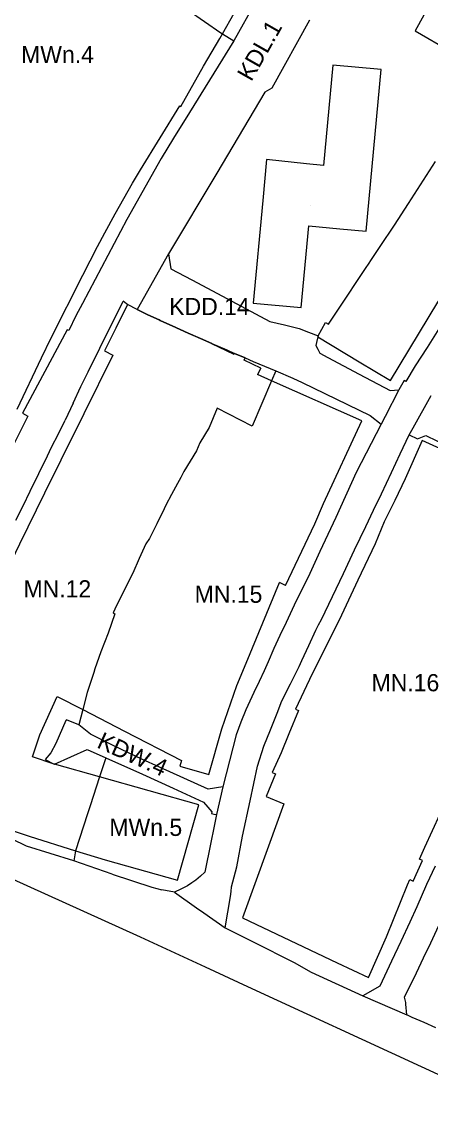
# Model space of a CAD drawing. Extents: x 7425067 to 7426806, y 5549054 to 5550619.
# Drawn here: x 7425656.7 to 7425775.6, y 5549655.4 to 5549976.3 of the extents above; entities that cross this region are included whole.
import ezdxf

# ---------------------------------------------------------------- set-up
doc = ezdxf.new("R2010")
doc.units = 0
for name, color, linetype in [('LIN_Linia Zabudowy Nieprzekraczalna', 7, 'Continuous'), ('LIN_linia zabudowy obowiązująca', 7, 'Continuous'), ('LIN_linie_rozgraniczajace', 7, 'Continuous'), ('TXT_Oznaczenia_przeznaczen', 7, 'Continuous')]:
    doc.layers.add(name, color=color, linetype=linetype)

msp = doc.modelspace()

# ---------------------------------------------------------------- linework, layer by layer
at = {"layer": 'LIN_Linia Zabudowy Nieprzekraczalna'}
for points in [[(7425742.7389, 5549884.8292), (7425754.78, 5549877.53), (7425763.82, 5549872.05), (7425777.59, 5549894.86), (7425782.97, 5549902.92), (7425793.7, 5549919.37), (7425798.37, 5549926.6), (7425805.55, 5549937.49), (7425810.05, 5549943.84), (7425813.5, 5549948.98), (7425818.04, 5549956.33), (7425822.22, 5549961.9), (7425831.24, 5549975.65), (7425835.44, 5549982.46), (7425845.17, 5549996.67), (7425848.22, 5550001.39), (7425860.25, 5550019.29)], [(7425688.8399, 5549929.4585), (7425691.2009, 5549933.3935), (7425702.6055, 5549951.9648), (7425702.86, 5549951.8), (7425709.48, 5549963.44), (7425710.7848, 5549965.653), (7425714.2539, 5549971.5633), (7425714.9902, 5549972.8797), (7425718.3675, 5549978.9183), (7425721.36, 5549984.23), (7425724.68, 5549989.11), (7425723.92, 5549989.66), (7425727.01, 5549994.19), (7425726.17, 5549994.77), (7425730.2813, 5550000.6279)], [(7425655.2768, 5549863.7294), (7425662.3503, 5549878.7355), (7425665.1746, 5549884.5158), (7425674.3584, 5549902.7629), (7425678.6779, 5549911.0696), (7425680.8016, 5549915.0743), (7425683.7745, 5549920.5636), (7425688.8399, 5549929.4585)], [(7425687.4166, 5549894.1603), (7425683.97, 5549887.33), (7425680.6584, 5549880.7578), (7425683.144, 5549879.4729)], [(7425726.15, 5549875.71), (7425721.3, 5549878.04), (7425721.5977, 5549878.6578), (7425718.5271, 5549879.9944), (7425718.36, 5549879.65), (7425711.86, 5549882.78), (7425711.9053, 5549882.8769), (7425708.59, 5549884.32), (7425704.98, 5549885.9), (7425700.35, 5549888.01), (7425699.66, 5549888.32), (7425696.87, 5549889.59), (7425696.5726, 5549889.7239), (7425693.25, 5549891.22), (7425690.155, 5549892.78), (7425687.4166, 5549894.1603)], [(7425683.144, 5549879.4729), (7425674.6885, 5549862.4106), (7425668.0393, 5549848.9323), (7425663.2786, 5549839.311), (7425655.9796, 5549824.5332), (7425648.9293, 5549809.9832), (7425646.0622, 5549804.0686), (7425642.7058, 5549797.2362), (7425636.6761, 5549784.4652)], [(7425726.15, 5549875.71), (7425725.2169, 5549873.8477)], [(7425755.5631, 5549860.3295), (7425729.2858, 5549872.0351), (7425725.2169, 5549873.8477)], [(7425733.37, 5549812.51), (7425741.88, 5549830.46), (7425744.41, 5549836.31), (7425755.5631, 5549860.3295)], [(7425773.11, 5549854.61), (7425768.09, 5549843.48), (7425765.11, 5549837.25), (7425762.06, 5549830.97), (7425759.4, 5549824.66), (7425754.35, 5549814.09), (7425749.57, 5549803.9), (7425746.41, 5549797.37), (7425741.09, 5549786.8), (7425736.24, 5549776.54), (7425737.1368, 5549776.1147)], [(7425779.596, 5549846.8457), (7425781.4, 5549850.92), (7425773.11, 5549854.61)], [(7425702.6, 5549759.97), (7425711.03, 5549757.56), (7425714.82, 5549770.83), (7425719.16, 5549783.44), (7425721.88, 5549789.88), (7425731.5999, 5549813.3544)], [(7425733.37, 5549812.51), (7425731.5999, 5549813.3544)], [(7425661.85, 5549769.11), (7425666.9725, 5549780.2432)], [(7425666.9725, 5549780.2432), (7425674.3987, 5549776.4089), (7425686.54, 5549770.14), (7425703.0633, 5549761.6086)], [(7425737.1368, 5549776.1147), (7425734.34, 5549769.4), (7425732.02, 5549763.83), (7425729.47, 5549758.13)], [(7425659.7764, 5549762.7317), (7425661.85, 5549769.11)], [(7425708.1, 5549748.75), (7425679.2737, 5549756.8742), (7425666.1673, 5549760.5777), (7425666.14, 5549760.57), (7425666.0929, 5549760.5928), (7425659.7764, 5549762.7317)], [(7425703.0633, 5549761.6086), (7425702.6, 5549759.97)], [(7425729.47, 5549758.13), (7425730.44, 5549757.74), (7425727.7, 5549751.2), (7425732.8299, 5549749.0202)], [(7425624.1991, 5549755.0945), (7425624.94, 5549754.67), (7425624.79, 5549753.35), (7425625.375, 5549753.025), (7425625.96, 5549752.7), (7425630.45, 5549750.59), (7425634.94, 5549748.48), (7425649.28, 5549742.72), (7425658.83, 5549739.66), (7425672.26, 5549735.38), (7425680.88, 5549732.76), (7425701.88, 5549726.85)], [(7425701.88, 5549726.85), (7425708.1, 5549748.75)], [(7425732.8299, 5549749.0202), (7425728.37, 5549736.75), (7425720.8009, 5549715.9258)], [(7425770.46, 5549726.57), (7425773.16, 5549732.55), (7425772.25, 5549732.96), (7425773.82, 5549736.43), (7425778.34, 5549746.1)], [(7425757.4618, 5549698.5049), (7425762.74, 5549710.31), (7425768.79, 5549725.5), (7425769.48, 5549727.01), (7425770.46, 5549726.57)], [(7425720.8009, 5549715.9258), (7425748.36, 5549702.83), (7425757.4618, 5549698.5049)]]:
    msp.add_lwpolyline(points, dxfattribs=at)
at = {"layer": 'LIN_linia zabudowy obowiązująca'}
for points in [[(7425827.66, 5550076.24), (7425771.07, 5549973.79)], [(7425771.07, 5549973.79), (7425781.44, 5549967.75), (7425838.25, 5550070.38), (7425827.66, 5550076.24)], [(7425761.17, 5549962.54), (7425747.06, 5549963.77), (7425744.3596, 5549934.5822), (7425739.39, 5549935.12), (7425727.84, 5549936.37), (7425726.71, 5549924.45), (7425723.95, 5549894.59)], [(7425740.1347, 5549917.0302), (7425749.154, 5549916.1833), (7425756.75, 5549915.47), (7425761.17, 5549962.54)], [(7425723.95, 5549894.59), (7425737.86, 5549893.33), (7425740.1347, 5549917.0302)]]:
    msp.add_lwpolyline(points, dxfattribs=at)
at = {"layer": 'LIN_linie_rozgraniczajace'}
for points in [[(7425724.58, 5549982.13), (7425718.26, 5549970.81)], [(7425705.05, 5549979.74), (7425714.5, 5549973.19)], [(7425740.32, 5549976.83), (7425729.34, 5549957.05)], [(7425714.5, 5549973.19), (7425714.9902, 5549972.8797), (7425718.26, 5549970.81)], [(7425718.26, 5549970.81), (7425705.42, 5549950.01)], [(7425727.33, 5549955.9), (7425713.33, 5549932.405)], [(7425729.34, 5549957.05), (7425727.33, 5549955.9)], [(7425705.42, 5549950.01), (7425700.73, 5549942.58)], [(7425700.73, 5549942.58), (7425697.2, 5549936.63)], [(7425697.2, 5549936.63), (7425687.22, 5549918.92)], [(7425769.12, 5549923.52), (7425776.93, 5549935.78)], [(7425713.33, 5549932.405), (7425699.33, 5549908.91)], [(7425764.985, 5549917.3), (7425769.12, 5549923.52)], [(7425687.22, 5549918.92), (7425674.26, 5549894.53)], [(7425760.85, 5549911.08), (7425764.985, 5549917.3)], [(7425758.14, 5549907.01), (7425760.85, 5549911.08)], [(7425699.33, 5549908.91), (7425690.155, 5549892.78)], [(7425699.33, 5549908.91), (7425699.97, 5549904.6)], [(7425757.61, 5549906.2), (7425758.14, 5549907.01)], [(7425699.97, 5549904.6), (7425706.055, 5549901.365)], [(7425754.49, 5549901.47), (7425756.59, 5549904.655)], [(7425756.59, 5549904.655), (7425757.61, 5549906.2)], [(7425706.055, 5549901.365), (7425712.14, 5549898.13)], [(7425750.88, 5549896.06), (7425754.49, 5549901.47)], [(7425712.14, 5549898.13), (7425720.47, 5549893.705)], [(7425674.26, 5549894.53), (7425672.31, 5549890.88)], [(7425679.3, 5549881.46), (7425686.14, 5549895.19)], [(7425687.06, 5549894.34), (7425686.14, 5549895.19)], [(7425690.155, 5549892.78), (7425687.4166, 5549894.1603), (7425687.06, 5549894.34)], [(7425745.86, 5549888.45), (7425750.88, 5549896.06)], [(7425672.31, 5549890.88), (7425670.34, 5549886.66)], [(7425690.155, 5549892.78), (7425693.25, 5549891.22)], [(7425693.25, 5549891.22), (7425696.5726, 5549889.7239), (7425696.87, 5549889.59)], [(7425720.47, 5549893.705), (7425728.8, 5549889.28)], [(7425696.87, 5549889.59), (7425699.66, 5549888.32)], [(7425699.66, 5549888.32), (7425700.35, 5549888.01)], [(7425700.35, 5549888.01), (7425704.98, 5549885.9)], [(7425728.8, 5549889.28), (7425733.04, 5549888.255)], [(7425733.04, 5549888.255), (7425737.28, 5549887.23)], [(7425742.79, 5549885.04), (7425744.93, 5549888.97)], [(7425744.93, 5549888.97), (7425745.86, 5549888.45)], [(7425669.85, 5549886.86), (7425656.82, 5549862.57)], [(7425670.34, 5549886.66), (7425669.85, 5549886.86)], [(7425704.98, 5549885.9), (7425706.42, 5549885.25)], [(7425706.42, 5549885.25), (7425708.59, 5549884.32)], [(7425737.28, 5549887.23), (7425740.035, 5549886.135)], [(7425740.035, 5549886.135), (7425742.79, 5549885.04)], [(7425742.79, 5549885.04), (7425742.7389, 5549884.8292), (7425742.32, 5549883.1)], [(7425777.9, 5549887.14), (7425774.54, 5549881.69)], [(7425675.98, 5549874.63), (7425679.3, 5549881.46)], [(7425708.59, 5549884.32), (7425711.9053, 5549882.8769), (7425716.24, 5549880.99)], [(7425742.32, 5549883.1), (7425742.12, 5549882.25)], [(7425742.12, 5549882.25), (7425742.72, 5549881.16)], [(7425774.54, 5549881.69), (7425771.07, 5549876.35)], [(7425716.24, 5549880.99), (7425718.5271, 5549879.9944), (7425721.5977, 5549878.6578), (7425723.89, 5549877.66)], [(7425742.72, 5549881.16), (7425743.32, 5549880.07)], [(7425743.32, 5549880.07), (7425745.6, 5549878.77)], [(7425745.6, 5549878.77), (7425754.705, 5549873.985)], [(7425730.5, 5549874.88), (7425729.2858, 5549872.0351), (7425723.65, 5549858.83)], [(7425723.89, 5549877.66), (7425727.195, 5549876.27)], [(7425727.195, 5549876.27), (7425730.5, 5549874.88)], [(7425730.5, 5549874.88), (7425735.47, 5549872.79)], [(7425771.07, 5549876.35), (7425768.29, 5549871.79)], [(7425673.84, 5549870.37), (7425675.98, 5549874.63)], [(7425735.47, 5549872.79), (7425738.16, 5549871.56)], [(7425738.16, 5549871.56), (7425757.9824, 5549861.8946)], [(7425754.705, 5549873.985), (7425763.81, 5549869.2)], [(7425767.8, 5549872.05), (7425766.26, 5549869.43)], [(7425768.29, 5549871.79), (7425767.8, 5549872.05)], [(7425671.55, 5549865.475), (7425673.84, 5549870.37)], [(7425766.26, 5549869.43), (7425762.28, 5549861.67)], [(7425763.81, 5549869.2), (7425765.035, 5549869.315)], [(7425765.035, 5549869.315), (7425766.26, 5549869.43)], [(7425671.55, 5549865.475), (7425669.26, 5549860.58)], [(7425770.44, 5549858.34), (7425775.65, 5549867.73)], [(7425656.82, 5549862.57), (7425658.37, 5549861.7)], [(7425713.47, 5549864.08), (7425711.09, 5549858.42)], [(7425723.65, 5549858.83), (7425713.47, 5549864.08)], [(7425658.37, 5549861.7), (7425654.19, 5549853.35)], [(7425667.285, 5549856.64), (7425669.26, 5549860.58)], [(7425762.28, 5549861.67), (7425761.1031, 5549859.3764), (7425753.89, 5549845.32)], [(7425757.9824, 5549861.8946), (7425761.1031, 5549859.3764)], [(7425665.31, 5549852.7), (7425667.285, 5549856.64)], [(7425709.775, 5549856.205), (7425708.46, 5549853.99)], [(7425711.09, 5549858.42), (7425709.775, 5549856.205)], [(7425766.705, 5549850.805), (7425769.28, 5549856.26)], [(7425769.28, 5549856.26), (7425770.44, 5549858.34)], [(7425769.28, 5549856.26), (7425771.69, 5549855.14)], [(7425771.69, 5549855.14), (7425774.16, 5549856.13)], [(7425774.16, 5549856.13), (7425783.69, 5549851.43)], [(7425664.695, 5549851.47), (7425665.31, 5549852.7)], [(7425708.46, 5549853.99), (7425707.43, 5549851.65)], [(7425661.585, 5549845.06), (7425664.08, 5549850.24)], [(7425664.08, 5549850.24), (7425664.695, 5549851.47)], [(7425707.43, 5549851.65), (7425705.615, 5549848.655)], [(7425764.13, 5549845.35), (7425766.705, 5549850.805)], [(7425705.615, 5549848.655), (7425703.8, 5549845.66)], [(7425659.09, 5549839.88), (7425661.585, 5549845.06)], [(7425702.855, 5549843.9), (7425701.91, 5549842.14)], [(7425703.8, 5549845.66), (7425702.855, 5549843.9)], [(7425753.89, 5549845.32), (7425747.93, 5549832.26)], [(7425762.7, 5549842.235), (7425764.13, 5549845.35)], [(7425656.99, 5549835.695), (7425659.09, 5549839.88)], [(7425701.91, 5549842.14), (7425700.215, 5549838.99)], [(7425761.27, 5549839.12), (7425762.7, 5549842.235)], [(7425700.215, 5549838.99), (7425698.52, 5549835.84)], [(7425758.96, 5549834.405), (7425761.27, 5549839.12)], [(7425654.89, 5549831.51), (7425656.99, 5549835.695)], [(7425698.01, 5549834.74), (7425695.87, 5549830.46)], [(7425698.52, 5549835.84), (7425698.01, 5549834.74)], [(7425756.65, 5549829.69), (7425758.96, 5549834.405)], [(7425695.87, 5549830.46), (7425693.73, 5549826.18)], [(7425747.93, 5549832.26), (7425743.28, 5549822.37)], [(7425753.4, 5549822.85), (7425756.65, 5549829.69)], [(7425692.67, 5549824.61), (7425690.795, 5549820.36)], [(7425693.73, 5549826.18), (7425692.67, 5549824.61)], [(7425690.795, 5549820.36), (7425688.92, 5549816.11)], [(7425743.28, 5549822.37), (7425740.37, 5549815.97)], [(7425750.15, 5549816.01), (7425753.4, 5549822.85)], [(7425688.92, 5549816.11), (7425684.19, 5549806.72)], [(7425740.37, 5549815.97), (7425735.82, 5549806.76)], [(7425746.95, 5549809.32), (7425750.15, 5549816.01)], [(7425743.75, 5549802.63), (7425746.95, 5549809.32)], [(7425683.69, 5549804.27), (7425681.71, 5549798.64)], [(7425684.19, 5549806.72), (7425683.21, 5549804.54)], [(7425683.21, 5549804.54), (7425683.69, 5549804.27)], [(7425734.65, 5549804.27), (7425733.48, 5549801.78)], [(7425735.82, 5549806.76), (7425734.65, 5549804.27)], [(7425733.48, 5549801.78), (7425731.695, 5549797.99)], [(7425742.12, 5549799.47), (7425742.935, 5549801.05)], [(7425742.935, 5549801.05), (7425743.75, 5549802.63)], [(7425681.71, 5549798.64), (7425679.63, 5549793.21)], [(7425731.695, 5549797.99), (7425729.91, 5549794.2)], [(7425740.115, 5549795.09), (7425742.12, 5549799.47)], [(7425738.11, 5549790.71), (7425740.115, 5549795.09)], [(7425679.63, 5549793.21), (7425677.85, 5549788.27)], [(7425729.91, 5549794.2), (7425728.25, 5549790.31)], [(7425677.85, 5549788.27), (7425677.54, 5549787.2)], [(7425728.25, 5549790.31), (7425727.16, 5549787.73)], [(7425734.755, 5549783.95), (7425737.3, 5549788.93)], [(7425737.3, 5549788.93), (7425738.11, 5549790.71)], [(7425677.54, 5549787.2), (7425676.61, 5549784.28)], [(7425727.16, 5549787.73), (7425725.65, 5549784.545)], [(7425676.61, 5549784.28), (7425675.68, 5549781.36)], [(7425725.65, 5549784.545), (7425724.14, 5549781.36)], [(7425732.21, 5549778.97), (7425734.755, 5549783.95)], [(7425675.68, 5549781.36), (7425674.3987, 5549776.4089), (7425673.25, 5549771.97)], [(7425722.945, 5549778.84), (7425721.75, 5549776.32)], [(7425724.14, 5549781.36), (7425722.945, 5549778.84)], [(7425730.9, 5549775.36), (7425732.21, 5549778.97)], [(7425721.75, 5549776.32), (7425720.375, 5549772.72)], [(7425728.98, 5549770.58), (7425730.9, 5549775.36)], [(7425669.47, 5549773.26), (7425666.49, 5549766.61)], [(7425669.65, 5549773.4), (7425669.47, 5549773.26)], [(7425673.25, 5549771.97), (7425669.65, 5549773.4)], [(7425720.375, 5549772.72), (7425719, 5549769.12)], [(7425676.61, 5549769.31), (7425673.25, 5549771.97)], [(7425683.57, 5549765.83), (7425676.61, 5549769.31)], [(7425719, 5549769.12), (7425717.035, 5549761.52)], [(7425727.06, 5549765.8), (7425728.98, 5549770.58)], [(7425666.49, 5549766.61), (7425665.05, 5549763.88)], [(7425691.54, 5549762.05), (7425683.57, 5549765.83)], [(7425725.18, 5549760.02), (7425727.06, 5549765.8)], [(7425665.05, 5549763.88), (7425663.45, 5549761.87)], [(7425666.14, 5549760.57), (7425666.1673, 5549760.5777), (7425675.67, 5549764.86)], [(7425675.67, 5549764.86), (7425681.08, 5549762.44)], [(7425681.08, 5549762.44), (7425679.2737, 5549756.8742), (7425676.53, 5549748.42)], [(7425681.08, 5549762.44), (7425691.74, 5549757.62)], [(7425663.45, 5549761.87), (7425666.0929, 5549760.5928), (7425666.14, 5549760.57)], [(7425696.73, 5549759.67), (7425691.54, 5549762.05)], [(7425703.76, 5549756.48), (7425696.73, 5549759.67)], [(7425717.035, 5549761.52), (7425715.07, 5549753.92)], [(7425723.08, 5549749.92), (7425725.18, 5549760.02)], [(7425691.74, 5549757.62), (7425700.62, 5549753.55)], [(7425710.79, 5549753.29), (7425703.76, 5549756.48)], [(7425700.62, 5549753.55), (7425709.5, 5549749.48)], [(7425715.07, 5549753.92), (7425710.79, 5549753.29)], [(7425715.07, 5549753.92), (7425713.22, 5549745.92)], [(7425720.79, 5549739.66), (7425723.08, 5549749.92)], [(7425676.53, 5549748.42), (7425675.78, 5549746.14)], [(7425709.5, 5549749.48), (7425710.71, 5549748.08)], [(7425710.71, 5549748.08), (7425711.92, 5549746.68)], [(7425711.92, 5549746.68), (7425711.76, 5549746.17)], [(7425675.78, 5549746.14), (7425672.26, 5549735.38)], [(7425711.76, 5549746.17), (7425712.49, 5549746.045)], [(7425712.845, 5549743.96), (7425712.47, 5549742)], [(7425712.49, 5549746.045), (7425713.22, 5549745.92)], [(7425713.22, 5549745.92), (7425712.845, 5549743.96)], [(7425657.99, 5549736.72), (7425645.79, 5549742.63)], [(7425712.47, 5549742), (7425711.64, 5549737.77)], [(7425711.64, 5549737.77), (7425709.89, 5549729.12)], [(7425719.13, 5549730.75), (7425720.79, 5549739.66)], [(7425691.12, 5549710.29), (7425636.47, 5549734.99)], [(7425671.81, 5549732.41), (7425657.99, 5549736.72)], [(7425672.26, 5549735.38), (7425671.81, 5549732.41)], [(7425682.88, 5549728.59), (7425671.81, 5549732.41)], [(7425718.395, 5549727.84), (7425719.13, 5549730.75)], [(7425776.85, 5549730.93), (7425774.32, 5549725.54)], [(7425682.88, 5549728.59), (7425694.5, 5549724.76)], [(7425708.585, 5549727.995), (7425707.28, 5549726.87)], [(7425709.89, 5549729.12), (7425708.585, 5549727.995)], [(7425717.66, 5549724.93), (7425718.395, 5549727.84)], [(7425694.5, 5549724.76), (7425697.36, 5549724.05)], [(7425701.03, 5549723.31), (7425697.36, 5549724.05)], [(7425702.925, 5549724.23), (7425701.03, 5549723.31)], [(7425704.82, 5549725.15), (7425702.925, 5549724.23)], [(7425706.05, 5549726.01), (7425704.82, 5549725.15)], [(7425707.28, 5549726.87), (7425706.05, 5549726.01)], [(7425717.49, 5549723.495), (7425717.66, 5549724.93)], [(7425774.32, 5549725.54), (7425771.49, 5549719.03)], [(7425701.03, 5549723.31), (7425707.48, 5549718.79)], [(7425716.535, 5549717.525), (7425717.32, 5549722.06)], [(7425717.32, 5549722.06), (7425717.49, 5549723.495)], [(7425707.48, 5549718.79), (7425709.61, 5549717.29)], [(7425715.75, 5549712.99), (7425716.535, 5549717.525)], [(7425771.49, 5549719.03), (7425769.47, 5549714.66)], [(7425709.61, 5549717.29), (7425715.75, 5549712.99)], [(7425769.47, 5549714.66), (7425766.815, 5549708.965)], [(7425715.75, 5549712.99), (7425723.95, 5549708.91)], [(7425775.58, 5549708.61), (7425777.89, 5549713.675)], [(7425710.07, 5549701.56), (7425691.12, 5549710.29)], [(7425723.95, 5549708.91), (7425735.83, 5549702.88)], [(7425766.815, 5549708.965), (7425764.16, 5549703.27)], [(7425773.485, 5549704.255), (7425775.58, 5549708.61)], [(7425722.37, 5549695.81), (7425710.07, 5549701.56)], [(7425735.83, 5549702.88), (7425740.75, 5549700.08)], [(7425764.16, 5549703.27), (7425760.79, 5549696.05)], [(7425771.39, 5549699.9), (7425773.485, 5549704.255)], [(7425740.75, 5549700.08), (7425755.78, 5549693.24)], [(7425767.91, 5549692.81), (7425771.39, 5549699.9)], [(7425772.86, 5549672.55), (7425722.37, 5549695.81)], [(7425760.79, 5549696.05), (7425755.78, 5549693.24)], [(7425755.78, 5549693.24), (7425768.6, 5549687.63)], [(7425768.27, 5549691.31), (7425767.91, 5549692.81)], [(7425768.31, 5549690.81), (7425768.27, 5549691.31)], [(7425768.6, 5549687.63), (7425768.31, 5549690.81)], [(7425770.15, 5549686.94), (7425768.6, 5549687.63)], [(7425773.61, 5549685.4), (7425770.15, 5549686.94)], [(7425777.07, 5549683.86), (7425773.61, 5549685.4)], [(7425810.13, 5549655.38), (7425772.86, 5549672.55)]]:
    msp.add_lwpolyline(points, dxfattribs=at)
at = {"layer": 'TXT_Oznaczenia_przeznaczen'}
msp.add_line((7425740.7, 5549922.92), (7425740.7, 5549922.92), dxfattribs=at)

# ---------------------------------------------------------------- texts
for s, rotation, p in [('KDL.1', 60.399123, (7425723.3641, 5549958.7861)), ('KDW.4', 335.826586, (7425678.1864, 5549765.5018))]:
    msp.add_text(s, height=5, rotation=rotation, dxfattribs=at).set_placement(p)
for s, p in [('MWn.4', (7425656.4378, 5549964.3583)), ('KDD.14', (7425699.5054, 5549891.1167)), ('MN.12', (7425657.1354, 5549809.0295)), ('MN.15', (7425706.9096, 5549807.4665)), ('MN.16', (7425758.3535, 5549781.7422)), ('MWn.5', (7425682.1058, 5549739.69))]:
    msp.add_text(s, height=5, dxfattribs=at).set_placement(p)

doc.saveas('drawing.dxf')
